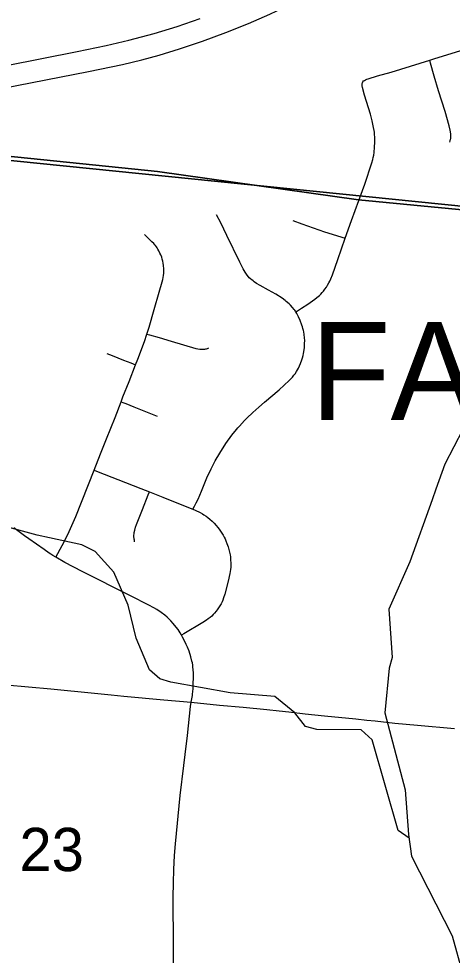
# Model space of a CAD drawing. Extents: x -1.4 to 35.4, y 0 to 22.
# Drawn here: x 28.891 to 29.309, y 13.771 to 14.677 of the extents above; entities that cross this region are included whole.
import ezdxf

# ---------------------------------------------------------------- set-up
doc = ezdxf.new("R2010")
doc.units = 0
for name, color, linetype in [('GM_X_City_Street', 7, 'Continuous'), ('GM_X_Corporation_Text', 7, 'Continuous'), ('GM_X_County_Road', 7, 'Continuous'), ('GM_X_Interstate_Route', 7, 'Continuous'), ('GM_X_Minor_River', 7, 'Continuous'), ('GM_X_Section', 7, 'Continuous'), ('GM_X_Section_Text', 7, 'Continuous'), ('SC_Scratch1', 7, 'Continuous')]:
    doc.layers.add(name, color=color, linetype=linetype)

msp = doc.modelspace()

# ---------------------------------------------------------------- linework, layer by layer
at = {"layer": 'GM_X_City_Street'}
for points in [[(29.22294, 14.61551), (29.22376, 14.61647), (29.22454, 14.61697), (29.22569, 14.6176), (29.22693, 14.61814), (29.22804, 14.61852), (29.2372, 14.62131), (29.25038, 14.62507), (29.28758, 14.63666), (29.29244, 14.63817), (29.32092, 14.64688)], [(29.30702, 14.55718), (29.30743, 14.55866), (29.30779, 14.56019), (29.3079, 14.56082), (29.30802, 14.56213), (29.30801, 14.56329), (29.30792, 14.56507), (29.30763, 14.56738), (29.30735, 14.56903), (29.30642, 14.57312), (29.30246, 14.5868), (29.29614, 14.60693), (29.29194, 14.62122), (29.28842, 14.63368), (29.28758, 14.63666)], [(29.15822, 14.39329), (29.15987, 14.39427), (29.16381, 14.3967), (29.16982, 14.40064), (29.17676, 14.40551), (29.17872, 14.40707), (29.17976, 14.40795), (29.18105, 14.40912), (29.18238, 14.41043), (29.18368, 14.41185), (29.18489, 14.4133), (29.18644, 14.41532), (29.1878, 14.41728), (29.18903, 14.41913), (29.19021, 14.42119), (29.19103, 14.42284), (29.19205, 14.4251), (29.19369, 14.42918), (29.19884, 14.44396), (29.206, 14.46445), (29.21217, 14.48157), (29.21922, 14.50094), (29.22481, 14.51679), (29.23163, 14.53734), (29.23259, 14.54057), (29.23304, 14.54245), (29.23351, 14.54488), (29.23385, 14.54716), (29.23439, 14.55258), (29.23455, 14.55726), (29.23459, 14.5595), (29.23445, 14.56242), (29.23436, 14.56443), (29.23417, 14.56683), (29.23393, 14.5687), (29.23348, 14.57147), (29.2328, 14.57476), (29.23218, 14.57783), (29.23038, 14.58438), (29.22468, 14.6028), (29.22254, 14.61016), (29.22226, 14.61166), (29.22223, 14.61303), (29.22231, 14.61394), (29.22254, 14.61473), (29.22294, 14.61551)], [(29.05883, 14.20234), (29.06045, 14.2054), (29.06203, 14.20856), (29.06381, 14.21227), (29.06705, 14.21998), (29.07246, 14.23294), (29.07639, 14.24139), (29.08039, 14.24912), (29.08477, 14.25664), (29.09083, 14.26604), (29.09663, 14.27415), (29.10092, 14.27958), (29.10219, 14.28109), (29.10374, 14.28278), (29.10863, 14.28821), (29.11084, 14.29043), (29.11687, 14.29601), (29.12243, 14.30096), (29.12813, 14.30581), (29.14223, 14.31802), (29.15199, 14.32695), (29.15349, 14.32845), (29.15493, 14.33003), (29.15648, 14.33195), (29.15758, 14.33347), (29.159, 14.33567), (29.16081, 14.33896), (29.16284, 14.34322), (29.16412, 14.34675), (29.16475, 14.3488), (29.16531, 14.3511), (29.16573, 14.35306), (29.16633, 14.35664), (29.16658, 14.35878), (29.16682, 14.36255), (29.16685, 14.36551), (29.16673, 14.36811), (29.16638, 14.3713), (29.16594, 14.3738), (29.1656, 14.37535), (29.16515, 14.37724), (29.16473, 14.3788), (29.16422, 14.38036), (29.1624, 14.385), (29.16086, 14.3885), (29.15989, 14.39043), (29.15915, 14.39177), (29.15822, 14.39329), (29.15784, 14.39387), (29.15721, 14.39475), (29.15654, 14.39564), (29.15493, 14.39761), (29.15299, 14.39974), (29.15184, 14.4009), (29.14904, 14.4034), (29.14793, 14.4043), (29.14494, 14.40652), (29.13903, 14.41038), (29.13199, 14.41432), (29.12376, 14.41878), (29.12045, 14.42073), (29.11792, 14.42241), (29.11697, 14.42309), (29.11574, 14.42406), (29.11497, 14.42474), (29.11439, 14.42526), (29.11336, 14.42629), (29.11252, 14.42725), (29.11139, 14.4287), (29.11062, 14.42975), (29.10945, 14.43154), (29.10754, 14.43483), (29.10428, 14.44128), (29.09177, 14.46696), (29.08576, 14.47923), (29.08177, 14.48698)], [(29.15526, 14.48142), (29.16407, 14.47847), (29.18613, 14.47058), (29.206, 14.46445)], [(28.92644, 14.15599), (28.92846, 14.15975), (28.93491, 14.17171), (28.93943, 14.18091), (28.94562, 14.19536), (28.9634, 14.24034), (28.96961, 14.25607), (28.97536, 14.27051), (28.98369, 14.29123), (28.98943, 14.3064), (28.99116, 14.31097), (28.99716, 14.32599), (29.00345, 14.34217), (29.00555, 14.34757), (29.0121, 14.36456), (29.01448, 14.37175), (29.0167, 14.37849), (29.02154, 14.39556), (29.02625, 14.41238), (29.02909, 14.42236), (29.02966, 14.42466), (29.0304, 14.42841), (29.03063, 14.4305), (29.03075, 14.4328), (29.03071, 14.4348), (29.03052, 14.438), (29.03021, 14.44046), (29.02983, 14.44235), (29.0293, 14.44433), (29.0287, 14.44623), (29.02781, 14.44843), (29.02705, 14.45007), (29.0259, 14.45238), (29.02509, 14.45388), (29.02436, 14.45508), (29.02369, 14.45608), (29.02283, 14.4573), (29.0221, 14.4582), (29.02103, 14.45935), (29.01931, 14.46109), (29.01322, 14.46691), (29.012, 14.46804)], [(29.01448, 14.37175), (29.01683, 14.37108), (29.02613, 14.36843), (29.038, 14.36477), (29.06185, 14.35788), (29.06372, 14.35748), (29.06549, 14.35724), (29.06724, 14.35709), (29.06849, 14.35707), (29.07039, 14.35724), (29.07123, 14.3574), (29.0721, 14.35765), (29.07289, 14.35794), (29.07413, 14.35854)], [(28.97561, 14.35302), (28.98087, 14.3511), (28.99187, 14.34669), (28.99883, 14.34397), (29.00345, 14.34217)], [(28.98943, 14.3064), (28.9912, 14.30569), (28.9942, 14.30449), (29.00168, 14.30137), (29.02441, 14.29253)], [(28.9634, 14.24034), (28.96747, 14.2387), (28.98649, 14.23109), (29.00849, 14.22254), (29.01697, 14.21924), (29.02993, 14.21418), (29.04665, 14.20744), (29.05883, 14.20234), (29.06111, 14.20139), (29.06584, 14.19913), (29.06807, 14.19792), (29.06956, 14.19703), (29.07163, 14.19565), (29.07338, 14.19435), (29.07532, 14.19273), (29.07739, 14.19085), (29.07932, 14.1889), (29.0814, 14.18658), (29.08295, 14.18475), (29.08423, 14.18314), (29.08561, 14.18123), (29.08681, 14.17941), (29.08801, 14.17736), (29.08915, 14.17527), (29.08994, 14.17366), (29.09072, 14.17188), (29.09177, 14.16927), (29.0929, 14.16616), (29.09373, 14.16342), (29.09431, 14.16106), (29.09481, 14.15836), (29.09508, 14.15648), (29.09529, 14.15422), (29.09551, 14.14977), (29.09537, 14.14631), (29.09516, 14.14429), (29.09455, 14.14028), (29.09308, 14.13298), (29.08979, 14.1203), (29.08858, 14.1167), (29.08776, 14.11457), (29.08709, 14.11304), (29.08608, 14.11103), (29.08432, 14.10813), (29.08236, 14.10515), (29.08139, 14.10388), (29.07965, 14.10183), (29.07844, 14.10052), (29.07705, 14.09919), (29.0755, 14.09784), (29.07361, 14.09635), (29.07214, 14.09528), (29.06858, 14.09295), (29.05013, 14.08211), (29.04769, 14.08067)], [(29.00254, 14.171), (29.00229, 14.17247), (29.00213, 14.17343), (29.00199, 14.1745), (29.00191, 14.17514), (29.00188, 14.17586), (29.00188, 14.17731), (29.00204, 14.1788), (29.00228, 14.18008), (29.00272, 14.18215), (29.00351, 14.18508), (29.00436, 14.18773), (29.01002, 14.20225), (29.01581, 14.2164), (29.01697, 14.21924)]]:
    msp.add_lwpolyline(points, dxfattribs=at)
at = {"layer": 'GM_X_County_Road'}
for points in [[(28.90037, 14.17368), (28.89604, 14.1768), (28.88574, 14.18457)], [(28.92644, 14.15599), (28.92352, 14.15776), (28.92158, 14.15901), (28.91997, 14.16011), (28.91508, 14.16339), (28.90037, 14.17368)], [(29.04769, 14.08067), (29.04648, 14.08286), (29.04448, 14.08602), (29.04269, 14.08844), (29.03992, 14.09189), (29.03763, 14.09455), (29.03601, 14.09623), (29.03414, 14.09804), (29.03176, 14.1), (29.02836, 14.10251), (29.02406, 14.10534), (29.02108, 14.10709), (29.01625, 14.10973), (28.99843, 14.11882), (28.952, 14.14224), (28.93523, 14.15097), (28.92644, 14.15599)], [(29.05846, 14.0235), (29.05906, 14.02887), (29.05924, 14.0343), (29.0594, 14.03904), (29.05932, 14.04405), (29.05915, 14.0474), (29.05895, 14.04984), (29.05871, 14.05163), (29.05835, 14.05387), (29.05799, 14.05563), (29.05691, 14.05974), (29.0551, 14.06508), (29.05349, 14.06917), (29.05234, 14.07169), (29.05128, 14.074), (29.0487, 14.07885), (29.04769, 14.08067)], [(28.84799, 14.0357), (28.86349, 14.03403), (28.87835, 14.03264), (28.92169, 14.02871), (28.96376, 14.02467), (28.97982, 14.02286), (28.99221, 14.02158), (29.03087, 14.01827), (29.05712, 14.01587)], [(29.05712, 14.01587), (29.05833, 14.02242), (29.05846, 14.0235)], [(29.05142, 13.96541), (29.05364, 13.98378), (29.05665, 14.01156), (29.05712, 14.01587)], [(29.05712, 14.01587), (29.08461, 14.01292), (29.10749, 14.011), (29.13039, 14.00879), (29.14213, 14.0076), (29.1514, 14.00662), (29.16745, 14.00476), (29.186, 14.0028), (29.21631, 13.99976), (29.22681, 13.99864), (29.23484, 13.99779), (29.254, 13.99572), (29.27568, 13.99368), (29.31157, 13.9904)], [(29.03999, 13.74729), (29.04005, 13.79077), (29.03992, 13.81687), (29.03994, 13.82742), (29.04005, 13.84108), (29.04033, 13.8541), (29.04104, 13.86772), (29.04194, 13.87884), (29.04668, 13.9258), (29.05014, 13.95478), (29.05142, 13.96541)]]:
    msp.add_lwpolyline(points, dxfattribs=at)
at = {"layer": 'GM_X_Interstate_Route'}
for points in [[(28.65328, 14.56621), (28.65426, 14.5664), (28.71095, 14.57724), (28.76523, 14.58776), (28.83412, 14.60135), (28.9579, 14.62552), (28.9907, 14.63247), (29.00942, 14.63692), (29.02619, 14.64144), (29.04578, 14.64738), (29.06812, 14.65492), (29.09083, 14.66329), (29.11272, 14.67208), (29.13317, 14.68106), (29.15333, 14.69068), (29.17315, 14.70097), (29.19591, 14.71368), (29.21672, 14.72604), (29.23662, 14.73869), (29.25614, 14.75191), (29.27373, 14.76464), (29.29039, 14.77757), (29.30615, 14.79064), (29.32335, 14.80584)], [(28.87886, 14.63147), (28.94715, 14.64486), (28.97515, 14.65067), (28.99694, 14.65585), (29.02156, 14.66251), (29.04357, 14.66923), (29.06593, 14.6769)]]:
    msp.add_lwpolyline(points, dxfattribs=at)
at = {"layer": 'GM_X_Minor_River'}
for points in [[(29.32819, 14.29627), (29.30214, 14.24594), (29.29369, 14.22182), (29.29007, 14.21164), (29.26839, 14.15173), (29.24813, 14.10583), (29.25136, 14.05908), (29.24851, 14.04889), (29.24423, 14.00571), (29.26398, 13.93129), (29.26729, 13.88795), (29.2699, 13.86702), (29.30933, 13.78993), (29.31923, 13.75405)], [(29.26771, 13.88455), (29.25712, 13.89195), (29.23194, 13.97938), (29.22151, 13.98909), (29.17865, 13.98957), (29.16771, 13.99245), (29.15735, 14.00557), (29.13795, 14.02152), (29.09477, 14.02506), (29.0377, 14.03532), (29.02676, 14.03858), (29.01707, 14.04713), (29.00403, 14.07776), (28.99632, 14.1098), (28.98254, 14.14158), (28.96436, 14.16169), (28.95159, 14.16802), (28.92024, 14.17473), (28.90853, 14.17724), (28.87307, 14.18707)]]:
    msp.add_lwpolyline(points, dxfattribs=at)
at = {"layer": 'GM_X_Section'}
for points in [[(29.59967, 15.43769), (29.51823, 14.47498), (28.5233, 14.5759), (28.61083, 15.54116)], [(29.51823, 14.47498), (29.4209, 13.46862), (28.42239, 13.55975), (28.5233, 14.5759)]]:
    msp.add_lwpolyline(points, close=True, dxfattribs=at)
at = {"layer": 'SC_Scratch1'}
for points in [[(27.90392, 14.63781), (28.52079, 14.58036), (28.54125, 14.57846), (28.58325, 14.57408), (28.65403, 14.56693), (29.02461, 14.52902), (29.21899, 14.50147), (30.07805, 14.41861), (30.53486, 14.3735), (31.03266, 14.32433), (31.28967, 14.29451), (31.28967, 19.35489)], [(24.48967, 13.05458), (31.28967, 13.05458), (31.28967, 14.29451), (31.03266, 14.32433), (30.53486, 14.3735), (30.07805, 14.41861), (29.21899, 14.50147), (29.02461, 14.52902), (28.65403, 14.56693), (28.58325, 14.57408), (28.54125, 14.57846), (28.52079, 14.58036), (27.90392, 14.63781)]]:
    msp.add_lwpolyline(points, dxfattribs=at)

# ---------------------------------------------------------------- texts
at = {"layer": 'GM_X_Corporation_Text'}
msp.add_text('FAIRBORN', height=0.094697, rotation=0.00001, dxfattribs=at).set_placement((29.17238, 14.2886))
at = {"layer": 'GM_X_Section_Text'}
msp.add_text('23', height=0.041856, rotation=0.00001, dxfattribs=at).set_placement((28.8913, 13.85256))

doc.saveas('drawing.dxf')
